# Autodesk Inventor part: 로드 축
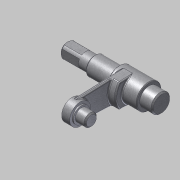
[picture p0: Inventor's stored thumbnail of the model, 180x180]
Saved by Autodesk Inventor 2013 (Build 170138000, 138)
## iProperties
Created: 2015-10
Part Number: 로드 축
Document SubType Name: Modeling
Designer: mdu
Density: 7.86 g/cm^3
Material: 강철, 연강
Mass: 151.797 g
Surface Area: 62.904 cm^2
Volume: 19.3125 cm^3
Author: mdu
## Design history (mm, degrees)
sketch "스케치1"
  geometry: L1 (-3.325, 13.5)-(-3.325, -13.5) reference; L2 (48.675, -15.7)-(48.675, 15.7) reference; L3 (48.675, 0)-(-26.325, 0); L4 (39.675, -18.06)-(39.675, 18.06) reference; L5 (15.675, 18.855)-(15.675, -18.855) reference; L6 (6.675, 15.7)-(6.675, -15.7) reference; L7 (3.675, -10)-(3.675, 10) reference; L8 (49.675, 7.5)-(39.675, 7.5); L9 (39.675, 7.5)-(39.675, 10); L10 (39.675, 10)-(15.675, 10); L11 (15.675, 10)-(15.675, 7.5); L12 (15.675, 7.5)-(-4.325, 7.5); L13 (-4.325, 7.5)-(-4.325, 6); L14 (-4.325, 6)-(-26.325, 6); L15 (-26.325, 6)-(-26.325, 0); L16 (48.675, 0)-(49.675, 0); L17 (49.675, 0)-(49.675, 7.5); 1 further point
  constraints: 22 end point, 7 perpendicular, 4 point on line, 2 parallel, 1 collinear, 1 midpoint
  dimensions: "d0" = 15 diameter of L8 L3; "d1" = 20 diameter of L10 L3; "d2" = 12 diameter of L14 L3; "d3" = 20 distance of L11.end L12.end; "d4" = 1 distance between parallel lines of L17 L2; "d5" = 75 distance of L3.start L3.end
revolve "회전1" sketch "스케치1" stored, may be unused: angle "d6" = 90 deg
chamfer "모따기1" distance "d7" = 1; stored, may be unused: second distance "d8" = 2, angle "d9" = 45 deg
node "작업 평면1"
sketch "스케치2"
  geometry: 1 further point
sketch "스케치3"
  geometry: L1 (9.993, -0.375)-(8.494, -40.319); L2 (-8.494, -40.319)-(-9.993, -0.375); C1 r 10 at (0, 0) reference; A1 r 8.5 centre (0, -40) between (8.494, -40.319) and (-8.494, -40.319); A2 r 10 centre (0, 0) between (-9.993, -0.375) and (9.993, -0.375) reference; 1 further point
  constraints: 4 end point, 4 point on circle, 4 tangent, 1 centre point, 1 vertical alignment
  dimensions: "d12" = 17 diameter of A1; "d22" = 40 distance of A1.centre A2.centre
  node "투영된 루프1"
extrude "돌출1" join sketch "스케치3" distance "d13" = 6.5; taper "d14" = 0 deg
node "작업 평면3"
  node "작업 평면2"
extrude "돌출2" join sketch "스케치3" stored distance "d17" = 6; taper "d18" = 0 deg
sketch "스케치7"
  geometry: L1 (-9.993, -0.375)-(-8.494, -40.319) reference; L2 (8.494, -40.319)-(9.993, -0.375) reference; A1 r 10 centre (0, 0) between (-9.993, -0.375) and (9.993, -0.375) reference; A2 r 15 centre (0, 0) between (-9.574, -11.547) and (9.574, -11.547); 1 further point
  constraints: 2 point on circle, 2 point on line, 1 centre point, 1 coincident
  dimensions: "d32" = 30 diameter of A2
extrude "돌출6" join sketch "스케치7" distance "d33" = 6; taper "d34" = 0 deg
sketch "스케치5"
  geometry: C1 r 5 at (0, 0) reference; C2 r 6.5 at (0, 0); 1 further point
  constraints: 1 centre point, 1 coincident
  dimensions: "d23" = 13 diameter of C2
  node "참조8"
extrude "돌출4" join sketch "스케치5" distance "d24" = 9; taper "d25" = 0 deg
extrude "돌출5" join sketch "스케치5" distance "d26" = 1; taper "d27" = 0 deg
fillet "모깎기1" dims "d28" = 1
chamfer "모따기2" distance "d29" = 1; stored, may be unused: second distance "d30" = 2, angle "d31" = 45 deg
chamfer "모따기3" distance "d35" = 0.5; stored, may be unused: second distance "d36" = 2, angle "d37" = 45 deg
sketch "스케치8"
  geometry: L1 (-3.25, 5.044)-(3.25, 5.044); L2 (5.044, 3.25)-(5.044, -3.25); L3 (3.25, -5.044)-(-3.25, -5.044); L4 (-5.044, -3.25)-(-5.044, 3.25); 2 further points
  constraints: 8 end point, 6 perpendicular, 1 horizontal, 9 other
  dimensions: "d38" = 6.5 distance of L3.start L3.end
extrude "돌출7" cut sketch "스케치8" distance "d39" = 15; taper "d40" = 0 deg
node "솔리드1"
node "참조1"
node "참조2"
node "참조3"
node "참조4"
node "참조5"
node "참조6"
other parameters: "d10" = -8.5, "d15" = -1, "d16" = -3
